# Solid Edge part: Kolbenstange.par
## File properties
Username: bmolnar
Dokumentum tartalom típus: 0
Author: bmolnar
Last saved by: bmolnar
Revision: 94
Sűrűség: 0,000 kg/m^3
Pontosság: 0,990
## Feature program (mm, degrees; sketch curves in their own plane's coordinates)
base feature "unnamed BaseFeature 1"
sketch for "unnamed Protrusion 1" plane through (23.3, 0, 0) normal (1, 0, 0) x-axis (0, -1, 0)
  circle centre (0, 0) radius 10
extrude "unnamed Protrusion 1" add finite 6.7 along +normal
sketch for "Furat_1" plane through (-245, 0, 0) normal (-1, 0, 0) x-axis (0, 1, 0)
hole "Furat_1" diameter 6 finite  VBottomAngle = 118 deg; ThreadDepth = 15 mm
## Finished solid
Body 1: solid body, 14 faces, 20 edges, 8 vertices.
  Faces by surface: plane 7, cylinder 4, cone 2, torus 1
  Edges by curve: circle 10, line 6, ellipse 2, intersection 2
Bounding box of the edges (mm; curved faces can reach further): 275.000 x 20.000 x 20.000, from (-245, -10, -10) to (30, 10, 10).
Cylindrical faces by radius (mm): R2.4585 x2, R5 x1, R10 x1
Conical faces (half-angle, radius in mm at the cone's reference point): 45 deg R2.8085 x1, 59 deg R2.4585 x1
Toroidal faces (ring radius, tube radius in mm): R3.8 r1.2 x1
Planar faces by outward normal: +x 1, +z 1, -x 2, -z 1, oblique 2
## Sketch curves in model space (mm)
circle centre (23.3, 0, 0) radius 10
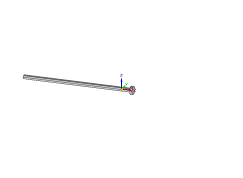
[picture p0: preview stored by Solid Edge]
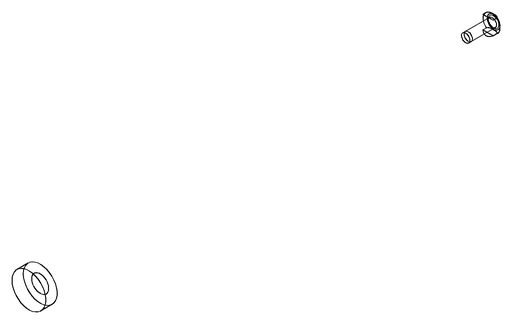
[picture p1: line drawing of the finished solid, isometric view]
